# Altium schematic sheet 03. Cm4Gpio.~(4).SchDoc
size A3; SheetNumber: 3; SheetTotal: 3
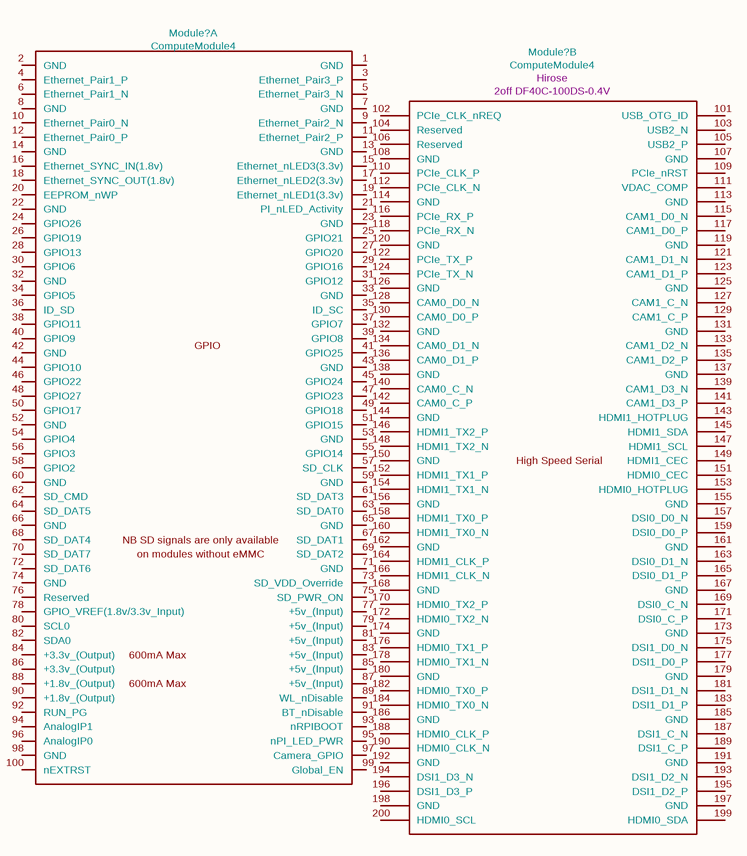
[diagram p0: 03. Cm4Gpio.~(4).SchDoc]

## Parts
(Parts that share a designator on the sheet are numbered #1, #2 ... from top to bottom, then left to right.)
Module?#1  ComputeModule4  [Raspberry-Pi-4-Compute-Module]  (part A of 2)
Module?#2  Field4: Hirose  Field5: 2off DF40C-100DS-0.4V  [Raspberry-Pi-4-Compute-Module]  (hidden comment: ComputeModule4)  (part B of 2)

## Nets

Not connected (* = marked no-connect by the designer): Module?#1 1(GND) 2(GND) 3(Ethernet_Pair3_P) 4(Ethernet_Pair1_P) 5(Ethernet_Pair3_N) 6(Ethernet_Pair1_N) 7(GND) 8(GND) 9(Ethernet_Pair2_N) 10(Ethernet_Pair0_N) 11(Ethernet_Pair2_P) 12(Ethernet_Pair0_P) 13(GND) 14(GND) 15(Ethernet_nLED3(3.3v)) 16(Ethernet_SYNC_IN(1.8v)) 17(Ethernet_nLED2(3.3v)) 18(Ethernet_SYNC_OUT(1.8v)) 19(Ethernet_nLED1(3.3v)) 20(EEPROM_nWP) 21(PI_nLED_Activity) 22(GND) 23(GND) 24(GPIO26) 25(GPIO21) 26(GPIO19) 27(GPIO20) 28(GPIO13) 29(GPIO16) 30(GPIO6) 31(GPIO12) 32(GND) 33(GND) 34(GPIO5) 35(ID_SC) 36(ID_SD) 37(GPIO7) 38(GPIO11) 39(GPIO8) 40(GPIO9) 41(GPIO25) 42(GND) 43(GND) 44(GPIO10) 45(GPIO24) 46(GPIO22) 47(GPIO23) 48(GPIO27) 49(GPIO18) 50(GPIO17) 51(GPIO15) 52(GND) 53(GND) 54(GPIO4) 55(GPIO14) 56(GPIO3) 57(SD_CLK) 58(GPIO2) 59(GND) 60(GND) 61(SD_DAT3) 62(SD_CMD) 63(SD_DAT0) 64(SD_DAT5) 65(GND) 66(GND) 67(SD_DAT1) 68(SD_DAT4) 69(SD_DAT2) 70(SD_DAT7) 71(GND) 72(SD_DAT6) 73(SD_VDD_Override) 74(GND) 75(SD_PWR_ON) 76(Reserved) 77(+5v_(Input)) 78(GPIO_VREF(1.8v/3.3v_Input)) 79(+5v_(Input)) 80(SCL0) 81(+5v_(Input)) 82(SDA0) 83(+5v_(Input)) 84(+3.3v_(Output)) 85(+5v_(Input)) 86(+3.3v_(Output)) 87(+5v_(Input)) 88(+1.8v_(Output)) 89(WL_nDisable) 90(+1.8v_(Output)) 91(BT_nDisable) 92(RUN_PG) 93(nRPIBOOT) 94(AnalogIP1) 95(nPI_LED_PWR) 96(AnalogIP0) 97(Camera_GPIO) 98(GND) 99(Global_EN) 100(nEXTRST); Module?#2 101(USB_OTG_ID) 102(PCIe_CLK_nREQ) 103(USB2_N) 104(Reserved) 105(USB2_P) 106(Reserved) 107(GND) 108(GND) 109(PCIe_nRST) 110(PCIe_CLK_P) 111(VDAC_COMP) 112(PCIe_CLK_N) 113(GND) 114(GND) 115(CAM1_D0_N) 116(PCIe_RX_P) 117(CAM1_D0_P) 118(PCIe_RX_N) 119(GND) 120(GND) 121(CAM1_D1_N) 122(PCIe_TX_P) 123(CAM1_D1_P) 124(PCIe_TX_N) 125(GND) 126(GND) 127(CAM1_C_N) 128(CAM0_D0_N) 129(CAM1_C_P) 130(CAM0_D0_P) 131(GND) 132(GND) 133(CAM1_D2_N) 134(CAM0_D1_N) 135(CAM1_D2_P) 136(CAM0_D1_P) 137(GND) 138(GND) 139(CAM1_D3_N) 140(CAM0_C_N) 141(CAM1_D3_P) 142(CAM0_C_P) 143(HDMI1_HOTPLUG) 144(GND) 145(HDMI1_SDA) 146(HDMI1_TX2_P) 147(HDMI1_SCL) 148(HDMI1_TX2_N) 149(HDMI1_CEC) 150(GND) 151(HDMI0_CEC) 152(HDMI1_TX1_P) 153(HDMI0_HOTPLUG) 154(HDMI1_TX1_N) 155(GND) 156(GND) 157(DSI0_D0_N) 158(HDMI1_TX0_P) 159(DSI0_D0_P) 160(HDMI1_TX0_N) 161(GND) 162(GND) 163(DSI0_D1_N) 164(HDMI1_CLK_P) 165(DSI0_D1_P) 166(HDMI1_CLK_N) 167(GND) 168(GND) 169(DSI0_C_N) 170(HDMI0_TX2_P) 171(DSI0_C_P) 172(HDMI0_TX2_N) 173(GND) 174(GND) 175(DSI1_D0_N) 176(HDMI0_TX1_P) 177(DSI1_D0_P) 178(HDMI0_TX1_N) 179(GND) 180(GND) 181(DSI1_D1_N) 182(HDMI0_TX0_P) 183(DSI1_D1_P) 184(HDMI0_TX0_N) 185(GND) 186(GND) 187(DSI1_C_N) 188(HDMI0_CLK_P) 189(DSI1_C_P) 190(HDMI0_CLK_N) 191(GND) 192(GND) 193(DSI1_D2_N) 194(DSI1_D3_N) 195(DSI1_D2_P) 196(DSI1_D3_P) 197(GND) 198(GND) 199(HDMI0_SDA) 200(HDMI0_SCL)

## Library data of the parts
Module?#1 = ComputeModule4-CM4: Part Description: 100 Position Connector Receptacle, Center Strip Contacts Surface Mount Gold; Field4: Hirose; Field5: 2off DF40C-100DS-0.4V
Module?#2 = ComputeModule4-CM4: Part Description: 100 Position Connector Receptacle, Center Strip Contacts Surface Mount Gold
